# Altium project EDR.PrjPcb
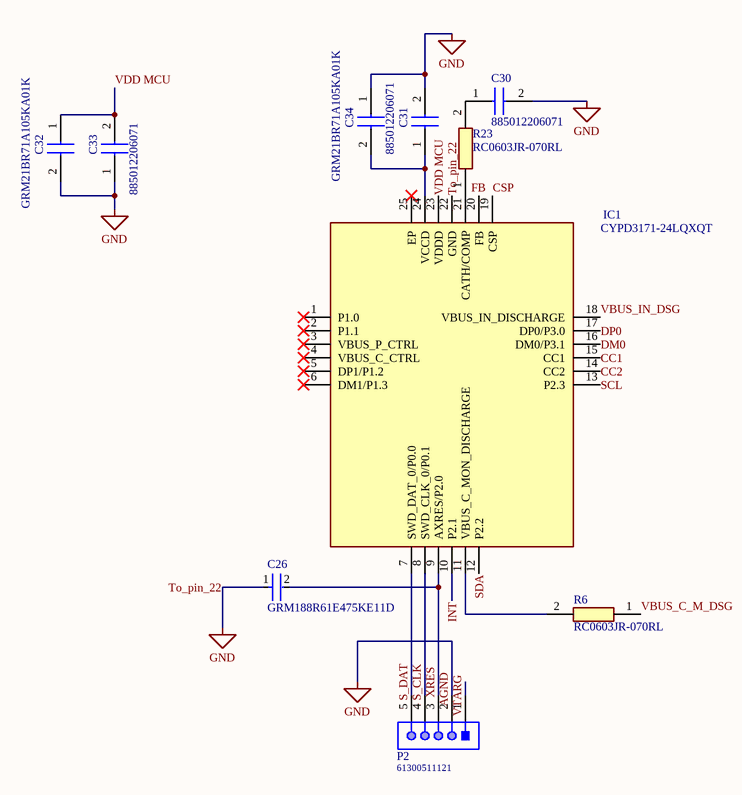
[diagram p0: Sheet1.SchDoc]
5 sheets, 89 parts. Net scope: global (net labels, ports and power ports of the same name join across sheets).
Board file: PCB1.PcbDoc
Sheets:
  Sheet1.SchDoc
  Sheet2.SchDoc
  Sheet3.SchDoc
  Sheet4.SchDoc
  Sheet5.SchDoc

## Sheet Sheet1.SchDoc
size A; SheetNumber: 1; SheetTotal: 5

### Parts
C26  GRM188R61E475KE11D  [FP-GRM188-0_15-IPC_C]
C30  885012206071  [CAPC1608X87N]
C31  885012206071  [CAPC1608X87N]
C32  GRM21BR71A105KA01K  [CAPC2012X145N]
C33  885012206071  [CAPC1608X87N]
C34  GRM21BR71A105KA01K  [CAPC2012X145N]
IC1  CYPD3171-24LQXQT  [QFN50P400X400X60-25N-D]
P2  61300511121  [61300511121]
R6  RC0603JR-070RL  [RESC1608X55N]
R23  RC0603JR-070RL  [RESC1608X55N]

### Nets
AGND: C26.1 C30.2 C31.2 C32.2 C33.1 C34.1 IC1.22(GND) P2.2  [also labelled GND, To_pin_22]
SCL: IC1.13(P2.3)
SDA: IC1.12(P2.2)
VBUS_C_M_DSG: R6.1  [project net TP_VBUS]
CC1: IC1.15(CC1)
CC2: IC1.14(CC2)
CSP: IC1.19(CSP)
DM0: IC1.16(DM0/P3.1)
DP0: IC1.17(DP0/P3.0)
FB: IC1.20(FB)
INT: IC1.10(P2.1)
S_CLK: IC1.8(SWD_CLK_0/P0.1) P2.4
S_DAT: IC1.7(SWD_DAT_0/P0.0) P2.5
VBUS_IN_DSG: IC1.18(VBUS_IN_DISCHARGE)
VDD MCU: C32.1 C33.2 IC1.23(VDDD)
VTARG: P2.1
XRES: C26.2 IC1.9(AXRES/P2.0) P2.3
NetC30_1: C30.1 R23.2
NetC31_1: C31.1 C34.2 IC1.24(VCCD)
NetIC1_11: IC1.11(VBUS_C_MON_DISCHARGE) R6.2
NetIC1_21: IC1.21(CATH/COMP) R23.1

Not connected (* = marked no-connect by the designer): IC1 1(P1.0)* 2(P1.1)* 3(VBUS_P_CTRL)* 4(VBUS_C_CTRL)* 5(DP1/P1.2)* 6(DM1/P1.3)* 25(EP)*

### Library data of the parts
C26 = CMP-2006-02523-2: Chip Multilayer Ceramic Capacitors for General Purpose, 0603, 4.7uF, X5R, 15%, 10%, 25V
C30 C31 C33 = 885012206071: Capacitor; Manufacturer_Name: Wurth Elektronik
C32 C34 = GRM21BR71A105KA01K: Capacitor; Manufacturer_Name: Murata Electronics
IC1 = CYPD3171-24LQXQT: Integrated Circuit; Manufacturer_Name: Cypress Semiconductor
P2 = CMP-1502-01068-1: THT Vertical Pin Header WR-PHD, Pitch 2.54 mm, Single Row, 5 pins; Manufacturer: Wurth Elektronik; Pin Number: 5; Contact Resistance: 20mOhm; Working Voltage: 250VAC; Pitch: 2.54mm; Withstanding Voltage: 500VAC; Rated Current: 3A; Gender: Male
R6 R23 = RC0603JR-070RL: Resistor; Manufacturer_Name: YAGEO

## Sheet Sheet2.SchDoc
size A; SheetNumber: 2; SheetTotal: 5
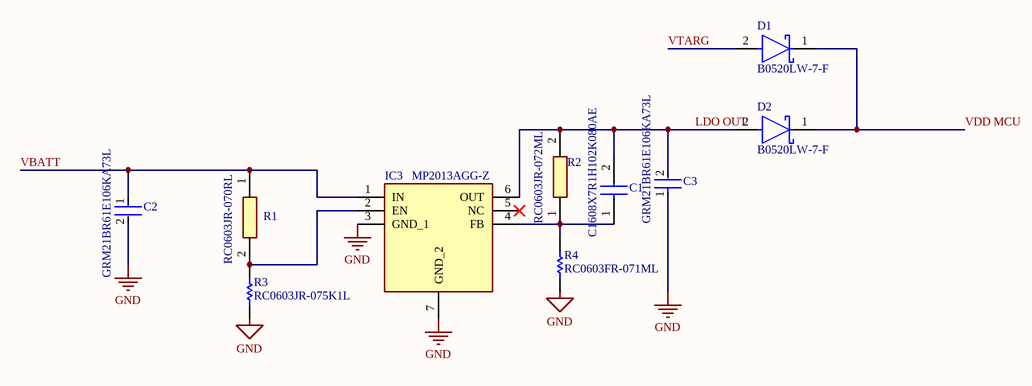
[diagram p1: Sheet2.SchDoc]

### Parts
C1  C1608X7R1H102K080AE  [CAPC1608X80N]
C2  GRM21BR61E106KA73L  [FP-GRM21B-0_15-IPC_C]
C3  GRM21BR61E106KA73L  [FP-GRM21B-0_15-IPC_C]
D1  B0520LW-7-F  [FP-SOD123-MFG]
D2  B0520LW-7-F  [FP-SOD123-MFG]
IC3  MP2013AGG-Z  [SON65P200X200X100-7N-D]
R1  RC0603JR-070RL  [RESC1608X55N]
R2  RC0603JR-072ML  [RESC1608X55N]
R3  RC0603JR-075K1L  [RESC1608X55X25LL10T15]
R4  RC0603FR-071ML  [RESC1608X55X25LL10T15]

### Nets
GND: C2.2 C3.1 IC3.3(GND_1) IC3.7(GND_2) R3.1 R4.1  [project net AGND]
LDO OUT: C1.2 C3.2 D2.2(A) IC3.6(OUT) R2.2
VBATT: C2.1 IC3.1(IN) R1.1
VDD MCU: D1.1(C) D2.1(C)
VTARG: D1.2(A)
NetC1_1: C1.1 IC3.4(FB) R2.1 R4.2
NetIC3_2: IC3.2(EN) R1.2 R3.2

Not connected (* = marked no-connect by the designer): IC3 5(NC)*

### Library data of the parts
C1 = C1608X7R1H102K080AE: Capacitor; Manufacturer_Name: TDK
C2 C3 = CMP-2007-03541-2: Chip Multilayer Ceramic Capacitors for General Purpose, 0805, 10uF, X5R, 15%, 10%, 25V
D1 D2 = CMP-12790-000026-1: DIODE SCHOTTKY 20V 500MA SOD123; Manufacturer: Diodes Inc.; Max Junction Temp: +125°C; Value: 170pF; Max Surge Forward Current: 5.5A; Forward Current: 0.5A; Standoff Height: 0mm; Peak Reverse Current: 250uA
IC3 = MP2013AGG-Z: Integrated Circuit; Manufacturer_Name: Monolithic Power Systems (MPS)
R1 = RC0603JR-070RL: Resistor; Manufacturer_Name: YAGEO
R2 = RC0603JR-072ML: Resistor; Manufacturer_Name: YAGEO
R3 = CMP-1012-00091-2: Chip Resistor, 5.1 KOhm, +/- 5%, 0.1 W, -55 to 155 degC, 0603 (1608 Metric), RoHS, Tape and Reel; Manufacturer: Yageo; Resistance: 5.1kOhms; Voltage Rating: 50V; Temperature Coefficient: 100PPM/C; Power Rating: 100mW
R4 = CMP-1659-00056-1: Chip Resistor, 1 MOhm, +/- 1%, 100 mW, -55 to 155 degC, 0603 (1608 Metric), RoHS, Tape and Reel; Voltage Rating (DC): 25 V; Tolerance: 20%; Case\Package: Radial; Capacitance: 1 mF

## Sheet Sheet3.SchDoc
size A; SheetNumber: 3; SheetTotal: 5
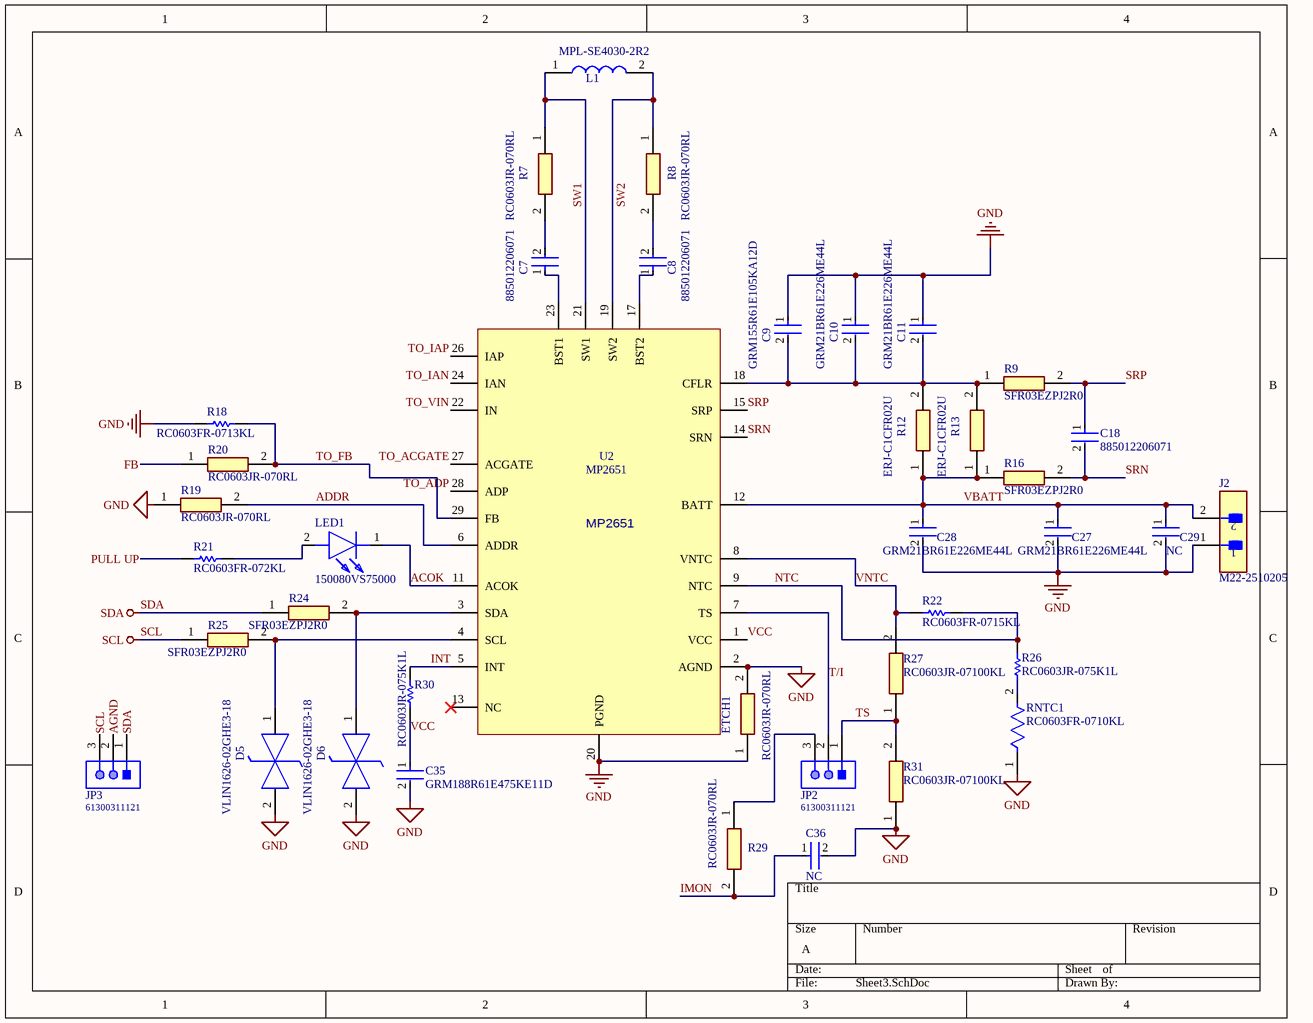
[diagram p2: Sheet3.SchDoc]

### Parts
C7  885012206071  [FP-885012206071-MFG]
C8  885012206071  [FP-885012206071-MFG]
C9  GRM155R61E105KA12D  [FP-GRM155-0_05-IPC_B]
C10  GRM21BR61E226ME44L  [FP-GRM21B-0_2-e0_2_0_7-IPC_B]
C11  GRM21BR61E226ME44L  [FP-GRM21B-0_2-e0_2_0_7-IPC_B]
C18  885012206071  [FP-885012206071-MFG]
C27  GRM21BR61E226ME44L  [FP-GRM21B-0_2-e0_2_0_7-IPC_B]
C28  GRM21BR61E226ME44L  [FP-GRM21B-0_2-e0_2_0_7-IPC_B]
C29  NC  [FP-GRM21B-0_2-e0_2_0_7-IPC_B]
C35  GRM188R61E475KE11D  [FP-GRM188-0_15-IPC_C]
C36  NC  [FP-GRM21B-0_2-e0_2_0_7-IPC_B]
D5  VLIN1626-02GHE3-18  [SOD2713X115N]
D6  VLIN1626-02GHE3-18  [SOD2713X115N]
ETCH1  RC0603JR-070RL  [RESC1608X55N]
J2  M22-2510205  [FP-M22-2510205-MFG]
JP2  61300311121  [61300311121]
JP3  61300311121  [61300311121]
L1  MPL-SE4030-2R2  [MPLSE40302R2]
LED1  150080VS75000  [LEDC2012X80N]
R7  RC0603JR-070RL  [RESC1608X55N]
R8  RC0603JR-070RL  [RESC1608X55N]
R9  SFR03EZPJ2R0  [RESC1608X55N]
R12  ERJ-C1CFR02U  [ERJC1]
R13  ERJ-C1CFR02U  [ERJC1]
R16  SFR03EZPJ2R0  [RESC1608X55N]
R18  RC0603FR-0713KL  [RESC1608X55X25LL10T15]
R19  RC0603JR-070RL  [RESC1608X55N]
R20  RC0603JR-070RL  [RESC1608X55N]
R21  RC0603FR-072KL  [RESC1608X55X25LL10T15]
R22  RC0603FR-0715KL  [RESC1608X55X25LL10T15]
R24  SFR03EZPJ2R0  [RESC1608X55N]
R25  SFR03EZPJ2R0  [RESC1608X55N]
R26  RC0603JR-075K1L  [RESC1608X55X25LL10T15]
R27  RC0603JR-07100KL  [RESC1608X55N]
R29  RC0603JR-070RL  [RESC1608X55N]
R30  RC0603JR-075K1L  [RESC1608X55X25LL10T15]
R31  RC0603JR-07100KL  [RESC1608X55N]
RNTC1  RC0603FR-0710KL  [FP-RC0603-0_55-IPC_C]
U2  MP2651  [MP2651]

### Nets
AGND: C9.1 C10.1 C11.1 C27.2 C28.2 C29.2 C35.2 C36.2 D5.2(K2) D6.2(K2) ETCH1.1 ETCH1.2 J2.1 JP3.2 R18.1 R19.1 R31.1 RNTC1.1 U2.2(AGND) U2.20(PGND)  [also labelled GND]
SCL: JP3.3 R25.1
SDA: JP3.1 R24.1
TO_ADP: U2.28(ADP)
ACOK: LED1.1(K) U2.11(ACOK)
ADDR: R19.2 U2.6(ADDR)
FB: R20.1
IMON: C36.1 R29.2
INT: R30.2 U2.5(INT)
NTC: R22.2 R26.2 U2.9(NTC)
PULL UP: R21.1  [project net CSP]
SRN: C18.2 R16.2 U2.14(SRN)
SRP: C18.1 R9.2 U2.15(SRP)
SW1: L1.1 R7.1 U2.21(SW1)
SW2: L1.2 R8.1 U2.19(SW2)
T/I: JP2.2 U2.7(TS)
TO_ACGATE: U2.27(ACGATE)
TO_FB: R18.2 R20.2 U2.29(FB)
TO_IAN: U2.24(IAN)
TO_IAP: U2.26(IAP)
TO_VIN: U2.22(IN)
TS: JP2.1 R27.1 R31.2
VBATT: C27.1 C28.1 C29.1 J2.2 R12.1 R13.1 R16.1 U2.12(BATT)
VCC: C35.1 R30.1 U2.1(VCC)
VNTC: R22.1 R27.2 U2.8(VNTC)
NetC7_1: C7.1 U2.23(BST1)
NetC7_2: C7.2 R7.2
NetC8_1: C8.1 U2.17(BST2)
NetC8_2: C8.2 R8.2
NetC9_2: C9.2 C10.2 C11.2 R9.1 R12.2 R13.2 U2.18(CFLR)
NetD5_1: D5.1(K1) R25.2 U2.4(SCL)
NetD6_1: D6.1(K1) R24.2 U2.3(SDA)
NetJP2_3: JP2.3 R29.1
NetLED1_2: LED1.2(A) R21.2
NetR26_1: R26.1 RNTC1.2

Not connected (* = marked no-connect by the designer): U2 13(NC)*

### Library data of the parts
C7 C8 C18 = CMP-207839-000033-1: CAP CER 0.1UF 25V X7R 0603; Capacitance: 100nF; Tolerance: 10%
C9 = CMP-2008-04581-2: Chip Multilayer Ceramic Capacitors for General Purpose, 0402, 1.0uF, X5R, 15%, 10%, 25V; Capacitance: 1uF
C10 C11 C27-C29 C36 = CMP-2007-03222-3: Chip Multilayer Ceramic Capacitors for General Purpose, 0805, 22uF, X5R, 15%, 20%, 25V
C35 = CMP-2006-02523-2: as C26 on sheet Sheet1
D5 D6 = VLIN1626-02GHE3-18: Diode ESD (Bi-directional); Manufacturer_Name: Vishay
ETCH1 R7 R8 R19 R20 R29 = RC0603JR-070RL: Resistor; Manufacturer_Name: YAGEO
J2 = CMP-15831-000005-1: CONN HEADER VERT 2POS 2MM; Manufacturer: Harwin; Conn Gender: Male; Current Rating: 2A; Number Of Contacts: 2; Conn Orientation: Vertical
JP2 JP3 = CMP-1502-01062-1: THT Vertical Pin Header WR-PHD, Pitch 2.54 mm, Single Row, 3 pins; Manufacturer: Wurth Elektronik; Withstanding Voltage: 500VAC; Working Voltage: 250VAC; Rated Current: 3A; Pitch: 2.54mm; Pin Number: 3; Gender: Male; Contact Resistance: 20mOhm
L1 = MPL-SE4030-2R2: Inductor; Manufacturer_Name: Monolithic Power Systems (MPS)
LED1 = 150080VS75000: LED; Manufacturer_Name: Wurth Elektronik
R9 R16 R24 R25 = SFR03EZPJ2R0: Resistor; Manufacturer_Name: ROHM Semiconductor
R12 R13 = ERJ-C1CFR02U: Resistor; Manufacturer_Name: Panasonic
R18 = CMP-2000-06927-1: Chip Resistor, 13 KOhm, +/- 1%, 0.1 W, -55 to 155 degC, 0603 (1608 Metric), RoHS, Tape and Reel; Manufacturer: Yageo; Resistance: 13kOhms; Temperature Coefficient: 100PPM/C; Voltage Rating: 50V; Power Rating: 100mW
R21 = CMP-2000-06937-1: Chip Resistor, 2 KOhm, +/- 1%, 50 V, -55 to 155 degC, 0603 (1608 Metric), RoHS, Tape and Reel; Manufacturer: Yageo; PCN Other: RC/AC0603/0805/120622/Jan/2013; Resistance (Ohms): 2k; Catalog Drawings: ThickFilmResistorTopThickFilmResistorSide; Kits: PHH4-KIT-ND-RESKIT1K-9.76K1/10W5700PCS; EDA / CAD Models: DownloadfromAcceleratedDesigns; HTML Datasheet: RCSeries,LSuffixDatasheet.html; Power (Watts): 0.1W,1/10W; Other Names: 311-2.00KHRCT; Temperature Coefficient: ±100ppm/°C; Online Catalog: RC0603Series
R22 = CMP-1659-00032-1: Chip Resistor, 15 KOhm, +/- 1%, 0.1 W, -55 to 155 degC, 0603 (1608 Metric), RoHS, Tape and Reel
R26 R30 = CMP-1012-00091-2: as R3 on sheet Sheet2
R27 R31 = RC0603JR-07100KL: Resistor; Manufacturer_Name: YAGEO
RNTC1 = CMP-2100-03664-2: RES 10K OHM 1% 1/10W 0603; Voltage Rating: 75V; Voltage Rating (DC): 50V; Resistance: 10kR; Power Rating: 100mW; Temperature Coefficient: 100ppm/°C
U2 = MP2651: MP2651 – BUCK-BOOST CHARGER FOR 1 TO 4 CELLS IN SERIES

## Sheet Sheet4.SchDoc
size A; SheetNumber: 4; SheetTotal: 5
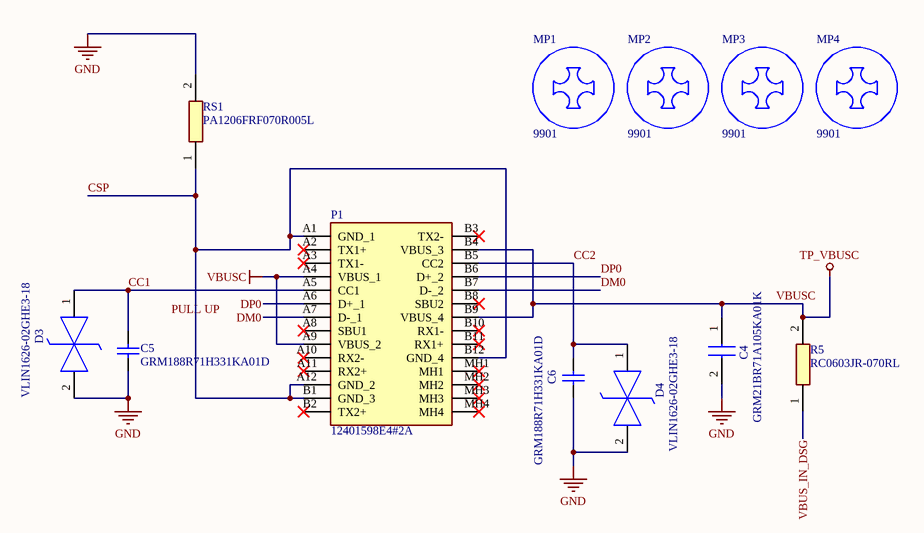
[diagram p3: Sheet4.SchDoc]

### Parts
C4  GRM21BR71A105KA01K  [CAPC2012X145N]
C5  GRM188R71H331KA01D  [CAPC1608X90X35NL10T15]
C6  GRM188R71H331KA01D  [CAPC1608X90X35NL10T15]
D3  VLIN1626-02GHE3-18  [SOD2713X115N]
D4  VLIN1626-02GHE3-18  [SOD2713X115N]
MP1  9901  [FP-9901-MFG]
MP2  9901  [FP-9901-MFG]
MP3  9901  [FP-9901-MFG]
MP4  9901  [FP-9901-MFG]
P1  12401598E4#2A  [12401598E42A]
R5  RC0603JR-070RL  [RESC1608X55N]
RS1  PA1206FRF070R005L  [RESC3216X65N]

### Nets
GND: C4.2 C5.1 C6.1 D3.2(K2) D4.2(K2) RS1.2  [project net AGND]
TP_VBUSC: C4.1 P1.A4(VBUS_1) P1.A9(VBUS_2) P1.B4(VBUS_3) P1.B9(VBUS_4) R5.2  [also labelled VBUSC]  [project net TO_ADP]
CC1: C5.2 D3.1(K1) P1.A5(CC1)
CC2: C6.2 D4.1(K1) P1.B5(CC2)
CSP: P1.A1(GND_1) P1.A12(GND_2) P1.B1(GND_3) P1.B12(GND_4) RS1.1  [also labelled PULL UP]
DM0: P1.A7(D-_1) P1.B7(D-_2)
DP0: P1.A6(D+_1) P1.B6(D+_2)
VBUS_IN_DSG: R5.1

Not connected (* = marked no-connect by the designer): P1 A2(TX1+)* A3(TX1-)* A8(SBU1)* A10(RX2-)* A11(RX2+)* B2(TX2+)* B3(TX2-)* B8(SBU2)* B10(RX1-)* B11(RX1+)* MH1* MH2* MH3* MH4*

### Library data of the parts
C4 = GRM21BR71A105KA01K: as C32 on sheet Sheet1
C5 C6 = CMP-2006-02914-1: Manufacturer: Murata
D3 D4 = VLIN1626-02GHE3-18: as D5 on sheet Sheet3
MP1-MP4 = CMP-19664-000002-1: MACHINE SCREW PAN PHILLIPS 4-40; Head Height: 0.065inch; Thread Size: #4-40; Outside Diameter: 0.212inch
P1 = 12401598E4#2A: Connector; Manufacturer_Name: Amphenol Communications Solutions
R5 = RC0603JR-070RL: Resistor; Manufacturer_Name: YAGEO
RS1 = PA1206FRF070R005L: Resistor; Manufacturer_Name: YAGEO

## Sheet Sheet5.SchDoc
size A; SheetNumber: 5; SheetTotal: 5
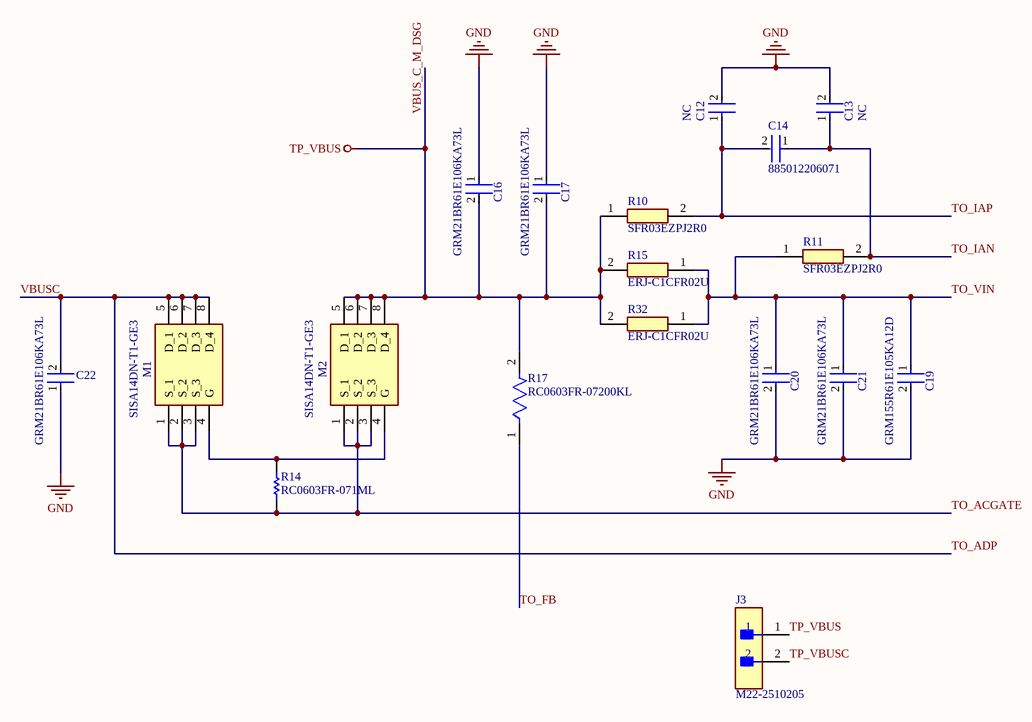
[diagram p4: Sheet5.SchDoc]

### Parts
C12  NC  [FP-885012206071-MFG]
C13  NC  [FP-885012206071-MFG]
C14  885012206071  [FP-885012206071-MFG]
C16  GRM21BR61E106KA73L  [FP-GRM21B-0_15-IPC_C]
C17  GRM21BR61E106KA73L  [FP-GRM21B-0_15-IPC_C]
C19  GRM155R61E105KA12D  [FP-GRM155-0_05-IPC_B]
C20  GRM21BR61E106KA73L  [FP-GRM21B-0_15-IPC_C]
C21  GRM21BR61E106KA73L  [FP-GRM21B-0_15-IPC_C]
C22  GRM21BR61E106KA73L  [FP-GRM21B-0_15-IPC_C]
J3  M22-2510205  [FP-M22-2510205-MFG]
M1  SISA14DN-T1-GE3  [SQ7414AENT1GE3]
M2  SISA14DN-T1-GE3  [SQ7414AENT1GE3]
R10  SFR03EZPJ2R0  [RESC1608X55N]
R11  SFR03EZPJ2R0  [RESC1608X55N]
R14  RC0603FR-071ML  [RESC1608X55X25LL10T15]
R15  ERJ-C1CFR02U  [ERJC1]
R17  RC0603FR-07200KL  [FP-RC0603-0_55-IPC_B]
R32  ERJ-C1CFR02U  [ERJC1]

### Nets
GND: C12.2 C13.2 C16.1 C17.1 C19.2 C20.2 C21.2 C22.1  [project net AGND]
TO_ADP: C22.2 J3.2 M1.5(D_1) M1.6(D_2) M1.7(D_3) M1.8(D_4)  [also labelled TP_VBUSC, VBUSC]
TP_VBUS: C16.2 C17.2 J3.1 M2.5(D_1) M2.6(D_2) M2.7(D_3) M2.8(D_4) R10.1 R15.2 R17.2 R32.2  [also labelled VBUS_C_M_DSG]
TO_ACGATE: M1.1(S_1) M1.2(S_2) M1.3(S_3) M2.1(S_1) M2.2(S_2) M2.3(S_3) R14.1
TO_FB: R17.1
TO_IAN: C13.1 C14.1 R11.2
TO_IAP: C12.1 C14.2 R10.2
TO_VIN: C19.1 C20.1 C21.1 R11.1 R15.1 R32.1
NetM1_4: M1.4(G) M2.4(G) R14.2

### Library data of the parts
C12-C14 = CMP-207839-000033-1: as C7 on sheet Sheet3
C16 C17 C20-C22 = CMP-2007-03541-2: as C2 on sheet Sheet2
C19 = CMP-2008-04581-2: as C9 on sheet Sheet3
J3 = CMP-15831-000005-1: as J2 on sheet Sheet3
M1 M2 = SISA14DN-T1-GE3: MOSFET (N-Channel); Manufacturer_Name: Vishay
R10 R11 = SFR03EZPJ2R0: as R9 on sheet Sheet3
R14 = CMP-1659-00056-1: as R4 on sheet Sheet2
R15 R32 = ERJ-C1CFR02U: Resistor; Manufacturer_Name: Panasonic
R17 = CMP-03412-037786-1: RES SMD 200K OHM 1% 1/10W 0603; Temperature Coefficient: 100ppm/°C; Voltage Rating: 50V; Resistance: 200kR; Max Power Dissipation: 100mW

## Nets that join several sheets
AGND: Sheet1 (8 pins), Sheet2 (6 pins), Sheet3 (20 pins), Sheet4 (6 pins), Sheet5 (8 pins)
SCL: Sheet1 (IC1.13), Sheet3 (JP3.3 R25.1)
SDA: Sheet1 (IC1.12), Sheet3 (JP3.1 R24.1)
TO_ADP: Sheet3 (U2.28), Sheet4 (6 pins), Sheet5 (6 pins)
TP_VBUS: Sheet1 (R6.1), Sheet5 (11 pins)
CC1: Sheet1 (IC1.15), Sheet4 (C5.2 D3.1 P1.A5)
CC2: Sheet1 (IC1.14), Sheet4 (C6.2 D4.1 P1.B5)
CSP: Sheet1 (IC1.19), Sheet3 (R21.1), Sheet4 (5 pins)
DM0: Sheet1 (IC1.16), Sheet4 (P1.A7 P1.B7)
DP0: Sheet1 (IC1.17), Sheet4 (P1.A6 P1.B6)
FB: Sheet1 (IC1.20), Sheet3 (R20.1)
INT: Sheet1 (IC1.10), Sheet3 (R30.2 U2.5)
TO_ACGATE: Sheet3 (U2.27), Sheet5 (7 pins)
TO_FB: Sheet3 (R18.2 R20.2 U2.29), Sheet5 (R17.1)
TO_IAN: Sheet3 (U2.24), Sheet5 (C13.1 C14.1 R11.2)
TO_IAP: Sheet3 (U2.26), Sheet5 (C12.1 C14.2 R10.2)
TO_VIN: Sheet3 (U2.22), Sheet5 (6 pins)
VBATT: Sheet2 (C2.1 IC3.1 R1.1), Sheet3 (8 pins)
VBUS_IN_DSG: Sheet1 (IC1.18), Sheet4 (R5.1)
VDD MCU: Sheet1 (C32.1 C33.2 IC1.23), Sheet2 (D1.1 D2.1)
VTARG: Sheet1 (P2.1), Sheet2 (D1.2)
